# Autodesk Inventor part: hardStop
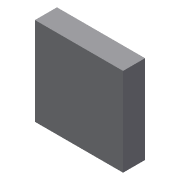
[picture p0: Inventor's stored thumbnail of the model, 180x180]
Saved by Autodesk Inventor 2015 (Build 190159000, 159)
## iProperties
Created: 2016-08
Part Number: hardStop
Material: EIFS, Exterior Insulation
Document SubType Name: Modeling
Designer: user
Density: 0.023 g/cm^3
Appearance: Gray
Author: user
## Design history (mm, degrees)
sketch "Sketch1"
  geometry: L1 (-9.525, 0)-(-34.925, 0); L2 (-34.925, 0)-(-34.925, -25.4); L3 (-34.925, -25.4)-(-9.525, -25.4); L4 (-9.525, -25.4)-(-9.525, 0); 1 further point
  constraints: 8 end point, 2 parallel, 1 horizontal, 1 perpendicular
  dimensions: "d0" = 25.4 distance of L3.end L2.end; "d1" = 25.4 distance of L2.end L1.end
extrude "Extrusion1" new body sketch "Sketch1" distance "d2" = 6.35; taper "d3" = 0 deg
body "Solid1"
